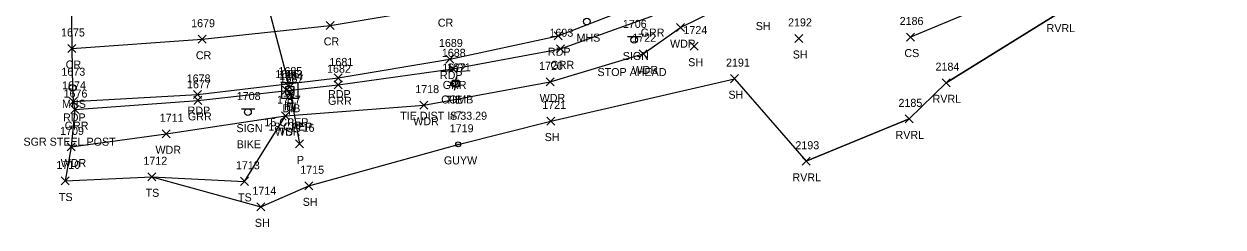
# Model space of a CAD drawing. Extents: x 1638344 to 1639591, y 610835 to 612202.
# Drawn here: x 1638344.1 to 1638643.8, y 611558.2 to 611608.8 of the extents above; entities that cross this region are included whole.
import ezdxf

# ---------------------------------------------------------------- set-up
doc = ezdxf.new("R2010")
doc.units = 0
for name, color, linetype in [('C_A', 7, 'Continuous'), ('C_C', 7, 'Continuous'), ('C_I', 7, 'Continuous'), ('CBP', 7, 'Continuous'), ('D_A', 7, 'Continuous'), ('D_C', 7, 'Continuous'), ('D_I', 7, 'Continuous'), ('D_TIC', 7, 'Continuous'), ('DCP', 7, 'Continuous'), ('DS', 7, 'Continuous'), ('L_A', 7, 'Continuous'), ('L_I', 7, 'Continuous'), ('L_TIC', 7, 'Continuous'), ('LAWA', 7, 'Continuous'), ('LAWE', 7, 'Continuous'), ('LELB', 7, 'Continuous'), ('LSOGP', 7, 'Continuous'), ('P_A', 7, 'Continuous'), ('P_I', 7, 'Continuous'), ('P_TIC', 7, 'Continuous'), ('PET', 7, 'Continuous'), ('PRC', 7, 'Continuous'), ('R_A', 7, 'Continuous'), ('R_C', 7, 'Continuous'), ('R_I', 7, 'Continuous'), ('R_TIC', 7, 'Continuous'), ('RGR', 7, 'Continuous'), ('S_A', 7, 'Continuous'), ('S_C', 7, 'Continuous'), ('S_I', 7, 'Continuous'), ('SSGN', 7, 'Continuous'), ('U_A', 7, 'Continuous'), ('U_C', 7, 'Continuous'), ('U_I', 7, 'Continuous'), ('UP', 7, 'Continuous'), ('UPGW', 7, 'Continuous'), ('USMH', 7, 'Continuous')]:
    doc.layers.add(name, color=color, linetype=linetype)

msp = doc.modelspace()

# ---------------------------------------------------------------- linework, layer by layer
at = {"layer": 'CBP'}
for radius in [0.625, 0.0833]:
    msp.add_circle((1638451.42, 611593.93), radius, dxfattribs=at)
at = {"layer": 'D_TIC'}
for points in [[(1638408.75, 611591.31), (1638410.75, 611593.31)], [(1638410.75, 611591.31), (1638408.75, 611593.31)], [(1638409.47, 611592.07), (1638411.47, 611594.07)], [(1638411.47, 611592.07), (1638409.47, 611594.07)], [(1638409.65, 611590.8), (1638411.65, 611592.8)], [(1638411.65, 611590.8), (1638409.65, 611592.8)], [(1638409.75, 611590.21), (1638411.75, 611592.21)], [(1638411.75, 611590.21), (1638409.75, 611592.21)], [(1638411.97, 611577.92), (1638413.97, 611579.92)], [(1638413.97, 611577.92), (1638411.97, 611579.92)]]:
    msp.add_lwpolyline(points, dxfattribs=at)
at = {"layer": 'DCP'}
for points in [[(1638403.34, 611620.04), (1638410.47, 611593.07)], [(1638410.75, 611591.21), (1638412.97, 611578.92)]]:
    msp.add_lwpolyline(points, dxfattribs=at)
at = {"layer": 'DS'}
for p, q in [((1638408.57, 611594.25), (1638412.57, 611594.25)), ((1638408.57, 611590.25), (1638408.57, 611594.25)), ((1638409.57, 611591.25), (1638409.57, 611593.25)), ((1638409.57, 611593.25), (1638411.57, 611593.25)), ((1638411.57, 611593.25), (1638411.57, 611591.25)), ((1638412.57, 611594.25), (1638412.57, 611590.25)), ((1638412.57, 611590.25), (1638408.57, 611590.25)), ((1638411.57, 611591.25), (1638409.57, 611591.25)), ((1638410.58, 611592.25), (1638410.58, 611592.25)), ((1638410.58, 611592.25), (1638410.58, 611592.25))]:
    msp.add_line(p, q, dxfattribs=at)
at = {"layer": 'L_TIC'}
for points in [[(1638507.25, 611606.89), (1638509.25, 611608.89)], [(1638509.25, 611606.89), (1638507.25, 611608.89)], [(1638536.8, 611604.2), (1638538.8, 611606.2)], [(1638538.8, 611604.2), (1638536.8, 611606.2)], [(1638564.75, 611604.55), (1638566.75, 611606.55)], [(1638566.75, 611604.55), (1638564.75, 611606.55)], [(1638497.86, 611600.36), (1638499.86, 611602.36)], [(1638499.86, 611600.36), (1638497.86, 611602.36)], [(1638510.65, 611602.28), (1638512.65, 611604.28)], [(1638512.65, 611602.28), (1638510.65, 611604.28)], [(1638520.72, 611594.17), (1638522.72, 611596.17)], [(1638522.72, 611594.17), (1638520.72, 611596.17)], [(1638474.66, 611593.37), (1638476.66, 611595.37)], [(1638476.66, 611593.37), (1638474.66, 611595.37)], [(1638573.66, 611593.16), (1638575.66, 611595.16)], [(1638575.66, 611593.16), (1638573.66, 611595.16)], [(1638443.06, 611587.57), (1638445.06, 611589.57)], [(1638445.06, 611587.57), (1638443.06, 611589.57)], [(1638408.5, 611584.94), (1638410.5, 611586.94)], [(1638410.5, 611584.94), (1638408.5, 611586.94)], [(1638408.5, 611584.94), (1638410.5, 611586.94)], [(1638410.5, 611584.94), (1638408.5, 611586.94)], [(1638474.79, 611583.61), (1638476.79, 611585.61)], [(1638476.79, 611583.61), (1638474.79, 611585.61)], [(1638564.4, 611584.15), (1638566.4, 611586.15)], [(1638566.4, 611584.15), (1638564.4, 611586.15)], [(1638378.62, 611580.44), (1638380.62, 611582.44)], [(1638380.62, 611580.44), (1638378.62, 611582.44)], [(1638354.93, 611577.15), (1638356.93, 611579.15)], [(1638356.93, 611577.15), (1638354.93, 611579.15)], [(1638538.63, 611573.58), (1638540.63, 611575.58)], [(1638540.63, 611573.58), (1638538.63, 611575.58)], [(1638375.11, 611569.72), (1638377.11, 611571.72)], [(1638377.11, 611569.72), (1638375.11, 611571.72)], [(1638353.44, 611568.68), (1638355.44, 611570.68)], [(1638355.44, 611568.68), (1638353.44, 611570.68)], [(1638398.22, 611568.58), (1638400.22, 611570.58)], [(1638400.22, 611568.58), (1638398.22, 611570.58)], [(1638414.31, 611567.46), (1638416.31, 611569.46)], [(1638416.31, 611567.46), (1638414.31, 611569.46)], [(1638402.34, 611562.24), (1638404.34, 611564.24)], [(1638404.34, 611562.24), (1638402.34, 611564.24)]]:
    msp.add_lwpolyline(points, dxfattribs=at)
at = {"layer": 'LAWA'}
msp.add_lwpolyline([(1638355.93, 611578.15), (1638379.62, 611581.44), (1638409.5, 611585.94), (1638444.06, 611588.57), (1638475.66, 611594.37), (1638498.86, 611601.36), (1638508.25, 611607.89), (1638527.03, 611617.21), (1638546.5, 611624.11), (1638573.22, 611641.38), (1638594.6, 611652.36), (1638613.43, 611662.84), (1638623.73, 611665.86), (1638642.74, 611667.09)], dxfattribs=at)
at = {"layer": 'LAWE'}
msp.add_lwpolyline([(1638639.67, 611638.46), (1638603.16, 611611.77), (1638574.66, 611594.16), (1638565.4, 611585.15), (1638539.63, 611574.58)], dxfattribs=at)
at = {"layer": 'LELB'}
for points in [[(1638614.95, 611626.06), (1638565.75, 611605.55)], [(1638354.44, 611569.68), (1638376.11, 611570.72), (1638399.22, 611569.58), (1638409.5, 611585.94)]]:
    msp.add_lwpolyline(points, dxfattribs=at)
at = {"layer": 'LSOGP'}
msp.add_lwpolyline([(1638355.88, 611617), (1638356.12, 611602.69), (1638356.22, 611592.9), (1638356.39, 611589.51), (1638356.81, 611587.46), (1638355.93, 611578.15), (1638354.44, 611569.68), (1638376.11, 611570.72), (1638403.34, 611563.24), (1638415.31, 611568.46), (1638452.68, 611578.8), (1638475.79, 611584.61), (1638521.72, 611595.17), (1638539.63, 611574.58), (1638565.4, 611585.15), (1638574.66, 611594.16), (1638603.16, 611611.77)], dxfattribs=at)
at = {"layer": 'P_TIC'}
for points in [[(1638419.62, 611607.46), (1638421.62, 611609.46)], [(1638421.62, 611607.46), (1638419.62, 611609.46)], [(1638387.66, 611604), (1638389.66, 611606)], [(1638389.66, 611604), (1638387.66, 611606)], [(1638476.61, 611604.87), (1638478.61, 611606.87)], [(1638478.61, 611604.87), (1638476.61, 611606.87)], [(1638355.12, 611601.69), (1638357.12, 611603.69)], [(1638357.12, 611601.69), (1638355.12, 611603.69)], [(1638449.6, 611599.07), (1638451.6, 611601.07)], [(1638451.6, 611599.07), (1638449.6, 611601.07)], [(1638421.64, 611594.34), (1638423.64, 611596.34)], [(1638423.64, 611594.34), (1638421.64, 611596.34)], [(1638355.39, 611588.51), (1638357.39, 611590.51)], [(1638357.39, 611588.51), (1638355.39, 611590.51)], [(1638386.53, 611590.22), (1638388.53, 611592.22)], [(1638388.53, 611590.22), (1638386.53, 611592.22)]]:
    msp.add_lwpolyline(points, dxfattribs=at)
at = {"layer": 'PET'}
msp.add_lwpolyline([(1638356.39, 611589.51), (1638387.53, 611591.22), (1638422.64, 611595.34), (1638450.6, 611600.07), (1638477.61, 611605.87), (1638499.25, 611614.17), (1638522.41, 611623.62), (1638545.7, 611634.45), (1638565.58, 611644.41), (1638587.93, 611655.84), (1638616.74, 611670.62), (1638633.38, 611678.5), (1638639.77, 611680.79), (1638643.67, 611682.22), (1638643.83, 611693.96), (1638643.72, 611707.5), (1638631.78, 611704.69), (1638616.32, 611698.49), (1638583.68, 611682.57)], dxfattribs=at)
at = {"layer": 'PRC'}
msp.add_lwpolyline([(1638356.12, 611602.69), (1638388.66, 611605), (1638420.62, 611608.46), (1638449.14, 611613.12), (1638473.93, 611619.15), (1638495.39, 611626.42), (1638517.33, 611635.58), (1638540.47, 611646.46), (1638560.01, 611656.08), (1638583.71, 611667.64), (1638612.7, 611681.66), (1638628.79, 611688.73), (1638636.08, 611691.34), (1638643.83, 611693.96)], dxfattribs=at)
at = {"layer": 'R_TIC'}
for points in [[(1638477.22, 611601.62), (1638479.22, 611603.62)], [(1638479.22, 611601.62), (1638477.22, 611603.62)], [(1638450.31, 611596.61), (1638452.31, 611598.61)], [(1638452.31, 611596.61), (1638450.31, 611598.61)], [(1638421.62, 611592.65), (1638423.62, 611594.65)], [(1638423.62, 611592.65), (1638421.62, 611594.65)], [(1638386.61, 611588.77), (1638388.61, 611590.77)], [(1638388.61, 611588.77), (1638386.61, 611590.77)], [(1638355.81, 611586.46), (1638357.81, 611588.46)], [(1638357.81, 611586.46), (1638355.81, 611588.46)]]:
    msp.add_lwpolyline(points, dxfattribs=at)
at = {"layer": 'RGR'}
msp.add_lwpolyline([(1638356.81, 611587.46), (1638387.61, 611589.77), (1638422.62, 611593.65), (1638451.31, 611597.61), (1638478.22, 611602.62), (1638500.77, 611610.66), (1638523.68, 611621.48), (1638546.21, 611632.67), (1638566.51, 611643.03), (1638588.48, 611654.34), (1638617.53, 611669.47), (1638633.84, 611677.48), (1638639.91, 611680.2), (1638642.7, 611681.41)], dxfattribs=at)
at = {"layer": 'SSGN'}
for p, q in [((1638495.01, 611605.68), (1638498.34, 611605.68)), ((1638496.65, 611604.84), (1638496.65, 611604.84)), ((1638398.45, 611587.69), (1638401.79, 611587.69)), ((1638400.1, 611586.86), (1638400.1, 611586.86))]:
    msp.add_line(p, q, dxfattribs=at)
for centre in [(1638496.65, 611604.84), (1638400.1, 611586.86)]:
    msp.add_circle(centre, 0.833, dxfattribs=at)
at = {"layer": 'UP'}
for p, q in [((1638452.27, 611595.66), (1638452.02, 611594.82)), ((1638451.19, 611593.16), (1638451.19, 611594.82)), ((1638451.19, 611594.82), (1638452.85, 611594.82)), ((1638452.85, 611593.16), (1638451.19, 611593.16)), ((1638451.77, 611592.32), (1638452.02, 611593.16)), ((1638452.02, 611593.99), (1638452.02, 611593.99)), ((1638452.85, 611594.82), (1638452.85, 611593.16))]:
    msp.add_line(p, q, dxfattribs=at)
msp.add_circle((1638452.02, 611593.99), 0.833, dxfattribs=at)
at = {"layer": 'UPGW'}
for radius in [0.625, 0.0833]:
    msp.add_circle((1638452.68, 611578.8), radius, dxfattribs=at)
at = {"layer": 'USMH'}
for p, q in [((1638356.22, 611592.9), (1638356.22, 611592.9)), ((1638357.06, 611592.9), (1638357.06, 611592.9))]:
    msp.add_line(p, q, dxfattribs=at)
for centre in [(1638484.81, 611609.39), (1638356.22, 611592.9)]:
    msp.add_circle(centre, 0.833, dxfattribs=at)

# ---------------------------------------------------------------- texts
at = {"layer": 'C_A'}
msp.add_text('TIE', height=2, dxfattribs=at).set_placement((1638449.5, 611588.93))
at = {"layer": 'C_C'}
msp.add_text('TIE DIST IS 33.29', height=2, dxfattribs=at).set_placement((1638438.17, 611584.93))
at = {"layer": 'C_I'}
msp.add_text('1672', height=2, dxfattribs=at).set_placement((1638448.68, 611596.93))
at = {"layer": 'D_A'}
for s, p in [('P', (1638409.84, 611588.07)), ('DIB', (1638408.75, 611586.8)), ('P', (1638409.12, 611587.31)), ('DI', (1638409.63, 611587.25)), ('P', (1638410.12, 611586.21)), ('P', (1638412.34, 611573.92))]:
    msp.add_text(s, height=2, dxfattribs=at).set_placement(p)
at = {"layer": 'D_C'}
for s, p in [('15 CPEP', (1638404.21, 611583.31)), ('18 CPEP', (1638405.21, 611582.21))]:
    msp.add_text(s, height=2, dxfattribs=at).set_placement(p)
at = {"layer": 'D_I'}
for s, p in [('1686', (1638406.95, 611595.31)), ('1685', (1638407.73, 611596.07)), ('1683', (1638407.84, 611595.25)), ('1684', (1638407.9, 611594.8)), ('1687', (1638408.01, 611594.21)), ('1716', (1638410.79, 611581.92))]:
    msp.add_text(s, height=2, dxfattribs=at).set_placement(p)
at = {"layer": 'L_A'}
for s, p in [('SH', (1638527.04, 611607.28)), ('RVRL', (1638599.73, 611606.77)), ('WDR', (1638505.61, 611602.89)), ('SH', (1638536.29, 611600.2)), ('CS', (1638564.19, 611600.55)), ('SH', (1638510.14, 611598.28)), ('WDR', (1638496.22, 611596.36)), ('WDR', (1638473.02, 611589.37)), ('SH', (1638520.21, 611590.17)), ('RVRL', (1638571.23, 611589.16)), ('WDR', (1638441.42, 611583.57)), ('WDR', (1638406.86, 611580.94)), ('TS', (1638407.9, 611580.94)), ('SH', (1638474.28, 611579.61)), ('RVRL', (1638561.97, 611580.15)), ('WDR', (1638376.99, 611576.44)), ('WDR', (1638353.3, 611573.15)), ('RVRL', (1638536.2, 611569.58)), ('TS', (1638352.85, 611564.68)), ('TS', (1638374.52, 611565.72)), ('TS', (1638397.63, 611564.58)), ('SH', (1638413.79, 611563.46)), ('SH', (1638401.83, 611558.24))]:
    msp.add_text(s, height=2, dxfattribs=at).set_placement(p)
at = {"layer": 'L_I'}
for s, p in [('2186', (1638563, 611608.55)), ('1724', (1638508.96, 611606.28)), ('2192', (1638535.11, 611608.2)), ('1722', (1638496.17, 611604.36)), ('1720', (1638472.88, 611597.37)), ('2191', (1638519.6, 611598.17)), ('2184', (1638571.97, 611597.16)), ('1718', (1638441.93, 611591.57)), ('1717', (1638407.37, 611588.94)), ('1717', (1638407.37, 611588.94)), ('1721', (1638473.66, 611587.61)), ('2185', (1638562.71, 611588.15)), ('1711', (1638378.07, 611584.44)), ('1709', (1638353.15, 611581.15)), ('2193', (1638536.94, 611577.58)), ('1710', (1638352.23, 611572.68)), ('1712', (1638373.98, 611573.72)), ('1713', (1638397.1, 611572.58)), ('1715', (1638413.18, 611571.46)), ('1714', (1638401.22, 611566.24))]:
    msp.add_text(s, height=2, dxfattribs=at).set_placement(p)
at = {"layer": 'P_A'}
for s, p in [('CR', (1638447.57, 611608.12)), ('CR', (1638419.05, 611603.46)), ('CR', (1638387.09, 611600)), ('RDP', (1638475.09, 611600.87)), ('CR', (1638354.55, 611597.69)), ('RDP', (1638448.09, 611595.07)), ('RDP', (1638420.13, 611590.34)), ('RDP', (1638353.88, 611584.51)), ('RDP', (1638385.02, 611586.22))]:
    msp.add_text(s, height=2, dxfattribs=at).set_placement(p)
at = {"layer": 'P_I'}
for s, p in [('1675', (1638353.38, 611605.69)), ('1679', (1638385.91, 611608)), ('1689', (1638447.85, 611603.07)), ('1681', (1638420.47, 611598.34)), ('1678', (1638384.79, 611594.22)), ('1674', (1638353.65, 611592.51))]:
    msp.add_text(s, height=2, dxfattribs=at).set_placement(p)
at = {"layer": 'R_A'}
for p in [(1638498.26, 611605.66), (1638475.7, 611597.62), (1638448.79, 611592.61), (1638420.11, 611588.65), (1638385.1, 611584.77), (1638354.3, 611582.46)]:
    msp.add_text('GRR', height=2, dxfattribs=at).set_placement(p)
at = {"layer": 'R_C'}
msp.add_text('SGR STEEL POST', height=2, dxfattribs=at).set_placement((1638344, 611578.46))
at = {"layer": 'R_I'}
for s, p in [('1693', (1638475.48, 611605.62)), ('1688', (1638448.57, 611600.61)), ('1682', (1638419.88, 611596.65)), ('1676', (1638354.02, 611590.46)), ('1677', (1638384.87, 611592.77))]:
    msp.add_text(s, height=2, dxfattribs=at).set_placement(p)
at = {"layer": 'S_A'}
for p in [(1638493.79, 611599.82), (1638397.24, 611581.84)]:
    msp.add_text('SIGN', height=2, dxfattribs=at).set_placement(p)
at = {"layer": 'S_C'}
for s, p in [('STOP AHEAD', (1638487.48, 611595.82)), ('BIKE', (1638397.29, 611577.84))]:
    msp.add_text(s, height=2, dxfattribs=at).set_placement(p)
at = {"layer": 'S_I'}
for s, p in [('1706', (1638493.81, 611607.82)), ('1708', (1638397.31, 611589.84))]:
    msp.add_text(s, height=2, dxfattribs=at).set_placement(p)
at = {"layer": 'U_A'}
for s, p in [('MHS', (1638482.23, 611604.39)), ('MHS', (1638353.64, 611587.9)), ('COMB', (1638448.41, 611588.99)), ('GUYW', (1638449.08, 611573.8))]:
    msp.add_text(s, height=2, dxfattribs=at).set_placement(p)
at = {"layer": 'U_C'}
msp.add_text('#7', height=2, dxfattribs=at).set_placement((1638450.56, 611584.99))
at = {"layer": 'U_I'}
for s, p in [('1671', (1638449.85, 611596.99)), ('1673', (1638353.48, 611595.9)), ('1719', (1638450.55, 611581.8))]:
    msp.add_text(s, height=2, dxfattribs=at).set_placement(p)

doc.saveas('drawing.dxf')
